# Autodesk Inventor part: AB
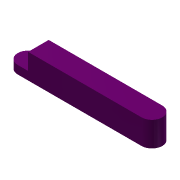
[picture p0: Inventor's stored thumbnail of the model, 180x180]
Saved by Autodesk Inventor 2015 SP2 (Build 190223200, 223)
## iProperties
Created: 2019-08
Part Number: AB
Material: 一般
Document SubType Name: Modeling
Designer: Kuan_Lun Hsu
Density: 1 g/cm^3
Appearance: 平滑 - 紫色
Author: Kuan_Lun Hsu
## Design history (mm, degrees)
sketch "草圖1"
  geometry: L1 (0, 0)-(30, 0); L2 (0, -2.5)-(30, -2.5); L3 (30, 2.5)-(0, 2.5); A1 r 2.5 centre (0, 0) between (0, 2.5) and (0, -2.5); A2 r 2.5 centre (30, 0) between (30, -2.5) and (30, 2.5); 1 further point
  constraints: 8 end point, 4 point on circle, 4 tangent, 2 centre point, 1 horizontal, 1 midpoint, 1 parallel
  dimensions: "d0" = 30 distance of L1.start L1.end (= AB_); "d1" = 5 distance between parallel lines of L2 L3 (= w_)
extrude "擠出1" new body sketch "草圖1" distance "d2" = 2 (= t_); taper "d3" = 0 deg
sketch "Sketch2"
  geometry: L1 (0, -2.5)-(30, -2.5) reference; L2 (30, 2.5)-(0, 2.5) reference; L3 (0, 2.5)-(2.5, 2.5); L4 (2.5, 2.5)-(2.5, -2.5); L5 (2.5, -2.5)-(0, -2.5); L6 (0, -2.5)-(0, 2.5); L7 (2.5, 2.5)-(30, 2.5); L8 (30, -2.5)-(2.5, -2.5); L9 (0, -2.5)-(30, -2.5) reference; A1 r 2.5 centre (0, 0) between (0, -2.5) and (0, 2.5); A2 r 2.5 centre (30, 0) between (30, -2.5) and (30, 2.5) reference; A3 r 2.5 centre (0, 0) between (0, 2.5) and (0, -2.5) reference; 3 further points
  constraints: 14 end point, 3 point on circle, 2 coincident, 2 horizontal, 2 parallel, 2 tangent, 1 centre point, 1 collinear, 1 midpoint, 1 perpendicular
extrude "Extrusion2" join sketch "Sketch2" distance "d4" = 4 (= 2 x t_); taper "d5" = 0 deg
node "實體1"
node "Projected Loop1"
other parameters: "AB_" = 30 [user parameter; used in 1 equation term], "w_" = 5 [user parameter; used in 1 equation term], "t_" = 2 [user parameter; used in 2 equation terms]
